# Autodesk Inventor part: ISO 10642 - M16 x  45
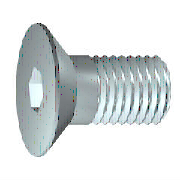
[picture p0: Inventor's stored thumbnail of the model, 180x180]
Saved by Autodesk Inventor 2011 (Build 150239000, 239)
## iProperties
Created: 2010-02
Part Number: ISO 10642 - M16 x  45
Material: Steel
Description: Hexagon Socket Countersunk Head Screw-1 - Product grade A
Document SubType Name: Modeling
Standard: ISO 10642
Designer: R. Koolhoven
Standard Revision: Second edition 2004-03-01
Standards Organization: ISO
Language: en-US
Size Designation: M16 x  45
Categories: <MemberInstance><Categories><Category DisplayName="Fasteners" InternalName="e4da775c-781d-43d5-af7c-5136215cf5a6" Mnemonic="FSTN"><Category DisplayName="Bolts"
Density: 7.85 g/cm^3
IsCustomPart: 0
Author: R. Koolhoven
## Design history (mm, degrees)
body "Solid1"
workplane "Work Plane1"
revolve "Body" stored, may be unused: angle "d13" = 90 deg
sketch "Sketch2"
  geometry: L1 (0, -20.307)-(0, 20.307) reference; L2 (-20.307, 0)-(20.307, 0) reference; L3 (5.774, 0)-(2.887, -5); L4 (2.887, -5)-(-2.887, -5); L5 (-2.887, -5)-(-5.774, 0); L6 (-5.774, 0)-(-2.887, 5); L7 (-2.887, 5)-(2.887, 5); L8 (2.887, 5)-(5.774, 0); A1 r 5.774 centre (0, 0) between (0, 5.774) and (5.774, 0) reference; 2 further points
  constraints: 12 end point, 2 coincident, 2 point on circle, 2 point on line, 12 other
extrude "Slot" join sketch "Sketch2" taper "d14" = 0 deg; stored distance "d30" = 10
feature "Thread" dims "d15" = 28.2 (= GEL), "d16" = 0
chamfer "Chamfer1" distance "d17" = 1.2269 (= -0.5 x SPD + 0.5 x GD); stored, may be unused: second distance "d18" = 1.2269 (= GUL), angle "d39" = 45 deg
sketch "Sketch1"
  geometry: L1 (45, 0)-(45, 8); L2 (45, 8)-(16.8, 8); L3 (16.8, 8)-(15.573, 8); L4 (0, 14.505)-(0, 5.774); L5 (0, 5.774)-(6.1, 5.774); L6 (6.1, 5.774)-(9.433, 0); L7 (9.433, 0)-(45, 0); L8 (0, 14.505)-(2.295, 14.505); L9 (2.295, 14.505)-(8.8, 8); L10 (15.573, 8)-(8.8, 8); L11 (16.8, 8)-(8.8, 8); L12 (8.8, 8)-(8.8, 8); L13 (-9, 0)-(54, 0) reference; L14 (0, -2.901)-(0, 17.406) reference
  constraints: 24 end point, 4 collinear, 3 parallel
  dimensions: "d0" = 45 distance between parallel lines of L4 L1 (= NLG); "d1" = 28.2 distance from line of L2.end L1 (= GEL); "d2" = 6.1 distance from line of L5.end L4 (= INTI); "d3" = 16 diameter of L2 L7 (= GD); "d6" = 8.8 distance from line of L9.end L4 (= KOH); "d7" = 45 deg angle of L9 L7 (= 0.5 x SEWI); "d8" = 11.54701 diameter of L5 L7 (= 1.1547 x SW); "d9" = 60 deg angle of L6 L7; "d10" = 29.01 diameter of L8 L7 (= KOD); "d11" = 16 diameter of L10 L7 (= BDM); "d12" = 1.2269 distance of L3.end L2.end (= GAL)
other parameters: "NLG" = 45 [user parameter; used in 1 equation term], "INTI" = 6.1 [user parameter; used in 1 equation term], "GEL" = 28.2 [user parameter; used in 2 equation terms], "GAL" = 1.2269 (= 0.61345 x PTC) [user parameter; used in 1 equation term], "KOH" = 8.8 [user parameter; used in 1 equation term], "KOD" = 29.01 [user parameter; used in 1 equation term], "GUL" = 1.2269 (= 0.61345 x PTC) [user parameter; used in 1 equation term], "SPD" = 13.5462 (= NND - 1.2269 x PTC) [user parameter; used in 1 equation term], "BDM" = 16 (= NND) [user parameter; used in 1 equation term], "GD" = 16 (= NND) [user parameter; used in 2 equation terms], "SEWI" = 90 deg [user parameter; used in 1 equation term], "d20" = 0, "d43" = 0, "d44" = 0, "TOA" = 30 deg [user parameter], "GD1" = 13.5462 (= THREADDIA - 1.2269 x PTC) [user parameter], "EPV" = 16.8 [user parameter], "THREADDIA" = 16 [user parameter; used in 1 equation term], "TPU" = 5 (computed from PTC) [user parameter], "PTC" = 2 [user parameter; used in 5 equation terms], "NND" = 16 [user parameter; used in 3 equation terms], "E0" = 11.55 [user parameter], "THREADDESC" = 12.345 [user parameter]
